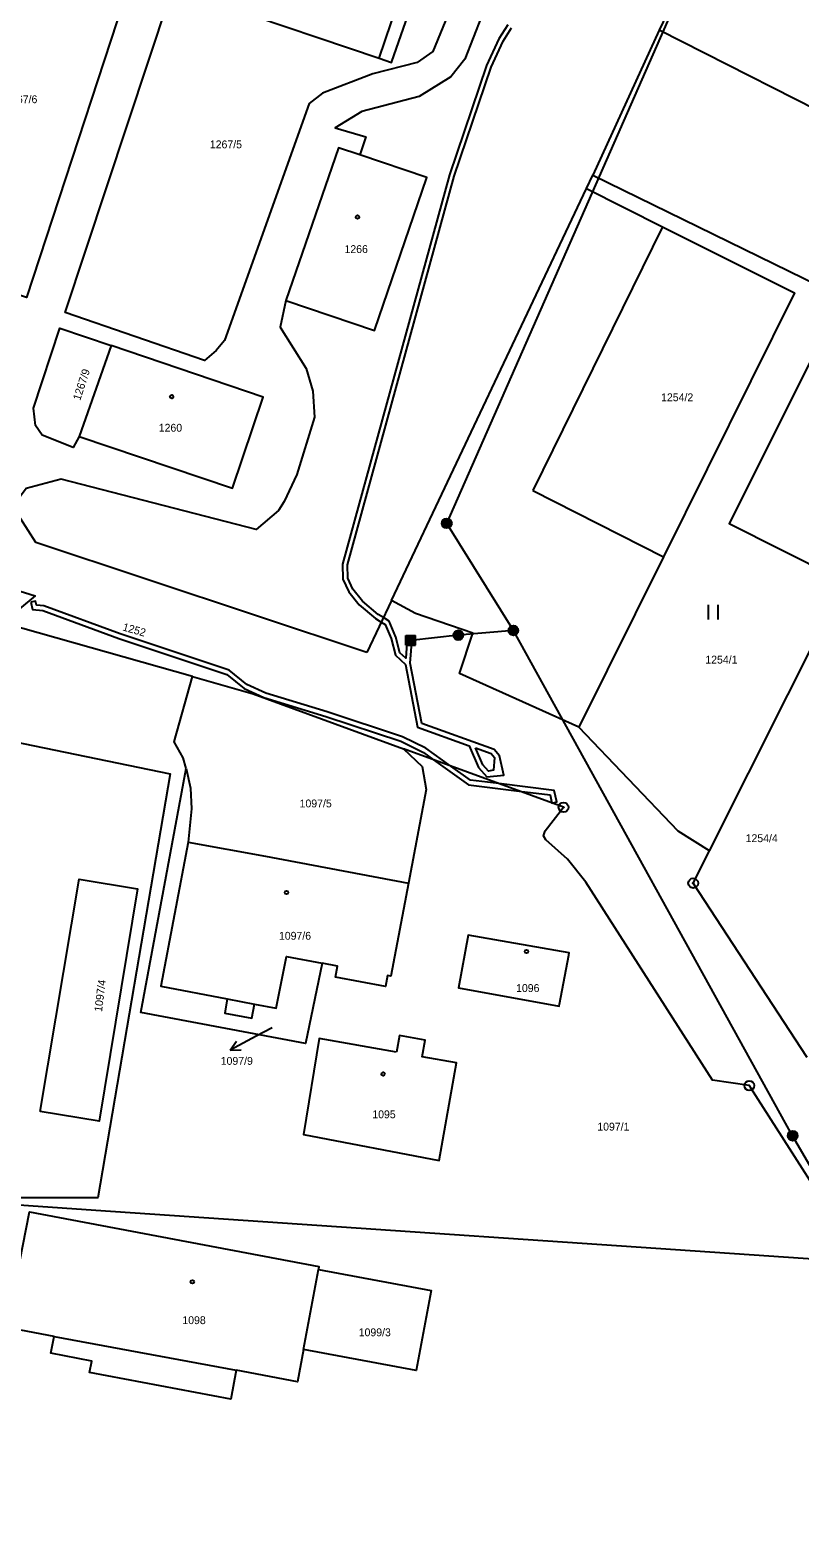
# Model space of a CAD drawing. Extents: x -587171 to -555306, y -1167727 to -1074732.
# Drawn here: x -560059.1 to -559980.4, y -1076879.4 to -1076725.4 of the extents above; entities that cross this region are included whole.
import ezdxf

# ---------------------------------------------------------------- set-up
doc = ezdxf.new("R2010")
doc.units = 0
for name, color, linetype in [('Hranice parcel', 7, 'Continuous'), ('Parcelní čísla', 7, 'Continuous'), ('Pop  PČ popisy', 7, 'Continuous'), ('Poz předměty', 7, 'Continuous'), ('Vnitřní kresba', 7, 'Continuous'), ('Věcná břemena k části', 7, 'Continuous'), ('Značky bodu BP', 7, 'Continuous'), ('Značky budov', 7, 'Continuous'), ('Značky kultur', 7, 'Continuous')]:
    doc.layers.add(name, color=color, linetype=linetype)

msp = doc.modelspace()

# ---------------------------------------------------------------- linework, layer by layer
at = {"layer": 'Hranice parcel'}
for p, q in [((-559988.04, -1076711.3), (-559994.8, -1076725.4)), ((-559994.8, -1076725.4), (-560001.56, -1076740.2)), ((-560002.22, -1076741.59), (-560001.56, -1076740.2)), ((-560001.56, -1076740.2), (-559969.04, -1076756.15)), ((-560022.13, -1076783.66), (-560002.22, -1076741.59)), ((-560050.77, -1076757.62), (-560054.04, -1076766.91)), ((-560022.13, -1076783.66), (-560024.65, -1076788.98)), ((-560042.48, -1076791.44), (-560061.62, -1076786.02)), ((-559992.83, -1076807.24), (-560002.98, -1076796.6)), ((-559989.66, -1076809.25), (-559992.83, -1076807.24)), ((-560031.13, -1076860.19), (-560029.61, -1076852.02))]:
    msp.add_line(p, q, dxfattribs=at)
for points in [[(-560022.02, -1076693.59), (-560025.51, -1076704.01), (-560027.17, -1076706.77), (-560028.36, -1076709.21), (-560027.41, -1076711.92), (-560015.24, -1076716.3), (-560013.13, -1076719.5), (-560012.66, -1076721.93), (-560012.94, -1076724.02), (-560014.63, -1076728.35), (-560016.06, -1076730.18), (-560019.32, -1076732.18), (-560025.17, -1076733.7), (-560027.91, -1076735.37), (-560024.76, -1076736.31), (-560025.39, -1076738.15)], [(-560051.12, -1076708.78), (-560047.98, -1076709.98), (-560046.8, -1076711.99), (-560046.85, -1076714.32), (-560059.45, -1076752.71), (-560074.04, -1076747.88), (-560074.96, -1076746.64), (-560075.12, -1076745.61), (-560066.89, -1076721.41), (-560067.44, -1076718.11), (-560068.91, -1076715.74), (-560070.48, -1076714.14), (-560069.9, -1076712.61)], [(-560023.4, -1076728.26), (-560022.14, -1076728.7), (-560018.53, -1076718.35), (-560017.27, -1076719.09), (-560015.96, -1076721.59), (-560016.12, -1076723.19), (-560017.93, -1076727.58), (-560019.53, -1076728.7), (-560024.06, -1076729.85), (-560029.19, -1076731.84), (-560030.56, -1076732.9), (-560039.21, -1076757.12), (-560040.04, -1076758.12), (-560041.26, -1076759.15), (-560055.48, -1076754.23), (-560042.7, -1076715.71), (-560041.54, -1076713.91), (-560040.05, -1076712.58), (-560036.01, -1076713.88)], [(-560036.01, -1076713.88), (-560039.17, -1076722.95), (-560023.4, -1076728.26)], [(-560023.4, -1076728.26), (-560020.33, -1076719.2), (-560036.01, -1076713.88)], [(-559957.13, -1076744.28), (-559973.96, -1076735.95), (-559994.8, -1076725.4)], [(-560025.39, -1076738.15), (-560027.54, -1076737.43), (-560032.93, -1076753.02)], [(-560032.93, -1076753.02), (-560023.86, -1076756.08), (-560018.53, -1076740.45), (-560025.39, -1076738.15)], [(-560002.22, -1076741.59), (-559994.44, -1076745.49), (-559980.96, -1076752.25), (-559994.33, -1076779.19), (-560002.98, -1076796.6)], [(-560032.93, -1076753.02), (-560033.5, -1076755.73), (-560030.86, -1076759.96), (-560030.19, -1076762.29), (-560030.02, -1076764.93), (-560031.82, -1076770.81), (-560033.09, -1076773.56), (-560033.67, -1076774.46), (-560035.98, -1076776.41), (-560055.9, -1076771.26), (-560059.48, -1076772.21), (-560060.84, -1076774.08)], [(-559956.07, -1076776.37), (-559960.56, -1076774.2), (-559959.85, -1076772.72), (-559961.71, -1076771.82), (-559962.42, -1076773.3), (-559967.2, -1076771), (-559965.43, -1076767.28), (-559971.14, -1076764.43), (-559972.96, -1076768.17), (-559974.48, -1076767.42), (-559969.76, -1076758.06), (-559976.96, -1076754.51), (-559987.65, -1076775.79), (-559976.87, -1076781.2), (-559977.88, -1076783.21)], [(-560054.04, -1076766.91), (-560054.68, -1076768.02), (-560057.83, -1076766.76), (-560058.51, -1076765.78), (-560058.73, -1076764.01), (-560056.04, -1076755.86), (-560050.77, -1076757.62)], [(-560054.04, -1076766.91), (-560038.39, -1076772.19), (-560035.25, -1076762.91), (-560050.77, -1076757.62)], [(-560024.65, -1076788.98), (-560058.48, -1076777.74), (-560060.84, -1076774.08)], [(-560063.97, -1076785.35), (-560060.63, -1076782.55), (-560058.56, -1076783.18), (-560061.76, -1076785.85), (-560061.62, -1076786.02)], [(-560002.98, -1076796.6), (-560007.39, -1076794.63), (-560015.2, -1076791.13), (-560013.83, -1076787), (-560019.69, -1076784.98), (-560022.13, -1076783.66)], [(-559989.66, -1076809.25), (-559977.66, -1076785.36), (-559978.85, -1076784.74), (-559977.88, -1076783.21)], [(-560043.11, -1076800.83), (-560043.44, -1076799.74), (-560044.33, -1076798.1), (-560042.48, -1076791.44)], [(-560042.48, -1076791.44), (-560036.28, -1076793.19), (-560020.92, -1076798.81)], [(-560072.67, -1076795.61), (-560044.77, -1076801.36), (-560052.14, -1076844.68), (-560070.59, -1076844.69)], [(-559974.06, -1076851.25), (-559985.47, -1076833.41), (-559985.58, -1076833.22), (-559989.34, -1076832.67), (-560002.27, -1076812.43), (-560004.14, -1076810.1), (-560006.38, -1076808.1), (-560006.59, -1076807.71), (-560006.43, -1076807.18), (-560004.56, -1076804.79), (-560020.92, -1076798.81)], [(-560020.92, -1076798.81), (-560019.02, -1076800.63), (-560018.6, -1076802.96), (-560020.4, -1076812.56)], [(-560029.22, -1076820.73), (-560030.92, -1076828.91), (-560047.75, -1076825.76), (-560043.11, -1076800.83)], [(-560043.11, -1076800.83), (-560042.68, -1076802.84), (-560042.57, -1076804.96), (-560042.91, -1076808.34)], [(-560042.91, -1076808.34), (-560045.71, -1076823.08), (-560038.94, -1076824.36), (-560039.16, -1076825.83), (-560036.4, -1076826.32), (-560036.13, -1076824.89), (-560033.91, -1076825.31), (-560032.86, -1076820.05), (-560029.22, -1076820.73)], [(-560042.91, -1076808.34), (-560035.03, -1076809.8), (-560020.4, -1076812.56)], [(-559979.67, -1076830.36), (-559991.31, -1076812.54), (-559989.66, -1076809.25)], [(-560058.04, -1076835.86), (-560054.07, -1076812.14), (-560048.1, -1076813.13), (-560052, -1076836.87), (-560058.04, -1076835.86)], [(-560020.4, -1076812.56), (-560022.19, -1076822.03), (-560022.54, -1076821.97), (-560022.76, -1076823.1), (-560027.87, -1076822.14), (-560027.66, -1076821.02), (-560029.22, -1076820.73)], [(-560004.03, -1076819.9), (-560003.99, -1076819.67), (-560014.32, -1076817.87), (-560015.29, -1076823.24), (-560005.02, -1076825.11), (-560004.98, -1076824.89), (-560004.03, -1076819.9)], [(-560021.63, -1076829.82), (-560029.52, -1076828.42), (-560031.12, -1076838.22), (-560017.28, -1076840.87), (-560015.5, -1076830.91), (-560019.01, -1076830.29), (-560018.7, -1076828.57), (-560021.32, -1076828.11), (-560021.63, -1076829.82)], [(-560070.59, -1076844.69), (-560052.35, -1076845.94), (-559974.06, -1076851.25)], [(-560031.13, -1076860.19), (-560031.74, -1076863.47), (-560038.02, -1076862.3), (-560038.57, -1076865.25), (-560052.99, -1076862.55), (-560052.76, -1076861.37), (-560056.96, -1076860.56), (-560056.6, -1076858.84), (-560061.44, -1076857.94), (-560059.14, -1076846.11), (-560029.55, -1076851.69), (-560029.61, -1076852.02)], [(-560029.61, -1076852.02), (-560018.08, -1076854.17), (-560019.61, -1076862.32), (-560031.13, -1076860.19)]]:
    msp.add_lwpolyline(points, dxfattribs=at)
at = {"layer": 'Pop  PČ popisy'}
for p, q in [((-560034.32, -1076827.31), (-560035.97, -1076828.19)), ((-560035.97, -1076828.19), (-560038.62, -1076829.6)), ((-560038.62, -1076829.6), (-560037.97, -1076828.69)), ((-560038.62, -1076829.6), (-560037.5, -1076829.57))]:
    msp.add_line(p, q, dxfattribs=at)
at = {"layer": 'Poz předměty'}
for p, q in [((-560016.49, -1076775.79), (-559987.84, -1076710.68)), ((-560009.68, -1076786.73), (-560016.49, -1076775.79)), ((-560020.68, -1076787.24), (-560019.68, -1076787.24)), ((-560020.68, -1076788.24), (-560020.68, -1076787.24)), ((-560020.68, -1076787.44), (-560019.68, -1076787.44)), ((-560020.68, -1076787.64), (-560019.68, -1076787.64)), ((-560020.48, -1076788.24), (-560020.48, -1076787.24)), ((-560020.28, -1076788.24), (-560020.28, -1076787.24)), ((-560015.31, -1076787.21), (-560020.18, -1076787.74)), ((-560020.08, -1076788.24), (-560020.08, -1076787.24)), ((-560019.88, -1076788.24), (-560019.88, -1076787.24)), ((-560019.68, -1076788.24), (-560019.68, -1076787.24)), ((-560009.68, -1076786.73), (-560015.31, -1076787.21)), ((-559981.15, -1076838.35), (-560009.68, -1076786.73)), ((-560020.68, -1076787.84), (-560019.68, -1076787.84)), ((-560020.68, -1076788.04), (-560019.68, -1076788.04)), ((-560020.68, -1076788.24), (-560019.68, -1076788.24)), ((-559952.18, -1076888.34), (-559981.15, -1076838.35))]:
    msp.add_line(p, q, dxfattribs=at)
for centre, radius in [((-560016.49, -1076775.79), 0.5), ((-560016.49, -1076775.79), 0.4), ((-560016.49, -1076775.79), 0.3), ((-560016.49, -1076775.79), 0.2), ((-560016.49, -1076775.79), 0.1), ((-560015.31, -1076787.21), 0.5), ((-560015.31, -1076787.21), 0.4), ((-560015.31, -1076787.21), 0.3), ((-560015.31, -1076787.21), 0.2), ((-560015.31, -1076787.21), 0.1), ((-560009.68, -1076786.73), 0.5), ((-560009.68, -1076786.73), 0.4), ((-560009.68, -1076786.73), 0.3), ((-560009.68, -1076786.73), 0.2), ((-560009.68, -1076786.73), 0.1), ((-559981.15, -1076838.35), 0.5), ((-559981.15, -1076838.35), 0.4), ((-559981.15, -1076838.35), 0.3), ((-559981.15, -1076838.35), 0.2), ((-559981.15, -1076838.35), 0.1)]:
    msp.add_circle(centre, radius, dxfattribs=at)
at = {"layer": 'Vnitřní kresba'}
for p, q in [((-559994.44, -1076745.49), (-560007.69, -1076772.44)), ((-560007.69, -1076772.44), (-559994.33, -1076779.19)), ((-560038.94, -1076824.36), (-560036.13, -1076824.89)), ((-560056.6, -1076858.84), (-560038.02, -1076862.3))]:
    msp.add_line(p, q, dxfattribs=at)
at = {"layer": 'Věcná břemena k části'}
msp.add_lwpolyline([(-560010.26, -1076724.86), (-560011.17, -1076726.29), (-560012.42, -1076729), (-560016.2, -1076740.17), (-560027.13, -1076779.97), (-560027.1, -1076781.5), (-560026.5, -1076782.77), (-560025.45, -1076784.1), (-560023.79, -1076785.49), (-560023.18, -1076785.87), (-560022.77, -1076786.12), (-560022.18, -1076787.56), (-560021.74, -1076789.26), (-560020.7, -1076790.22), (-560019.49, -1076796.61), (-560014.21, -1076798.5), (-560013.24, -1076800.74), (-560012.39, -1076801.67), (-560010.67, -1076801.52), (-560011.11, -1076799.53), (-560011.65, -1076798.88), (-560019.05, -1076796.23), (-560020.22, -1076790.08), (-560020.03, -1076787.55), (-560020.53, -1076787.51), (-560020.68, -1076789.56), (-560021.3, -1076789), (-560021.7, -1076787.4), (-560022.37, -1076785.78), (-560022.96, -1076785.41), (-560023.49, -1076785.09), (-560025.09, -1076783.74), (-560026.08, -1076782.51), (-560026.6, -1076781.38), (-560026.63, -1076780.03), (-560015.72, -1076740.31), (-560011.96, -1076729.18), (-560010.73, -1076726.53), (-560009.86, -1076725.16)], dxfattribs=at)
for points in [[(-560058.98, -1076783.82), (-560058.82, -1076784.59), (-560057.78, -1076784.7), (-560050.01, -1076787.55), (-560038.96, -1076791.24), (-560037.19, -1076792.67), (-560035.18, -1076793.59), (-560028.85, -1076795.52), (-560021.2, -1076798.05), (-560018.88, -1076799.19), (-560017.83, -1076799.94), (-560014.26, -1076802.49), (-560009.11, -1076803.13), (-560005.94, -1076803.52), (-560005.74, -1076804.36), (-560005.26, -1076804.24), (-560005.53, -1076803.07), (-560011.18, -1076802.37), (-560014.08, -1076802.01), (-560016.07, -1076800.58), (-560018.62, -1076798.75), (-560021.02, -1076797.59), (-560028.71, -1076795.04), (-560034.99, -1076793.13), (-560036.91, -1076792.25), (-560038.72, -1076790.8), (-560049.85, -1076787.07), (-560057.66, -1076784.2), (-560058.41, -1076784.13), (-560058.5, -1076783.72)], [(-560013.56, -1076798.73), (-560011.95, -1076799.3), (-560011.6, -1076799.72), (-560011.72, -1076801.01), (-560012.21, -1076801.11), (-560012.82, -1076800.46)]]:
    msp.add_lwpolyline(points, close=True, dxfattribs=at)
at = {"layer": 'Značky bodu BP'}
for centre, radius in [((-560004.56, -1076804.79), 0.5), ((-560004.56, -1076804.79), 0.0303), ((-559991.31, -1076812.54), 0.5), ((-559991.31, -1076812.54), 0.0303), ((-559985.58, -1076833.22), 0.5), ((-559985.58, -1076833.22), 0.0303)]:
    msp.add_circle(centre, radius, dxfattribs=at)
at = {"layer": 'Značky budov'}
for centre in [(-560025.61, -1076744.49), (-560044.6, -1076762.84), (-560032.87, -1076813.5), (-560008.34, -1076819.52), (-560023, -1076832.04), (-560042.49, -1076853.27)]:
    msp.add_circle(centre, 0.175, dxfattribs=at)
at = {"layer": 'Značky kultur'}
for p, q in [((-559989.76, -1076785.61), (-559989.76, -1076784.11)), ((-559988.76, -1076785.61), (-559988.76, -1076784.11))]:
    msp.add_line(p, q, dxfattribs=at)

# ---------------------------------------------------------------- texts
at = {"layer": 'Parcelní čísla'}
for s, p in [('1267/6', (-560061.61, -1076732.86)), ('1267/5', (-560040.7, -1076737.47)), ('1266', (-560026.94, -1076748.17)), ('1254/2', (-559994.59, -1076763.31)), ('1260', (-560045.92, -1076766.42)), ('1254/1', (-559990.07, -1076790.11)), ('1097/5', (-560031.53, -1076804.8)), ('1254/4', (-559985.95, -1076808.35)), ('1097/6', (-560033.64, -1076818.32)), ('1096', (-560009.41, -1076823.66)), ('1097/9', (-560039.59, -1076831.1)), ('1095', (-560024.1, -1076836.56)), ('1097/1', (-560001.11, -1076837.82)), ('1098', (-560043.51, -1076857.59)), ('1099/3', (-560025.49, -1076858.83))]:
    msp.add_text(s, height=0.803, dxfattribs=at).set_placement(p)
for s, rotation, p in [('1267/9', 72, (-560053.95, -1076763.29)), ('1252', 344, (-560049.68, -1076786.71)), ('1097/4', 83, (-560051.72, -1076825.72))]:
    msp.add_text(s, height=0.803, rotation=rotation, dxfattribs=at).set_placement(p)

doc.saveas('drawing.dxf')
